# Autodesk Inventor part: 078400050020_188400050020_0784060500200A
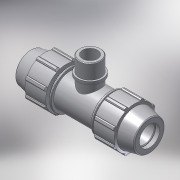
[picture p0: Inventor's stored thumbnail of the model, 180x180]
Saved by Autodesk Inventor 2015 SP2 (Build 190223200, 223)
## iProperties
Created: 2017-02
Part Number: 078400050020_188400050020_0784060500200A
Material: PVC-Piping
Description: PLASSON TEE WITH THREADED MALE OFFTAKE 50-2"
Document SubType Name: Modeling
Designer: KIM
Mass: 92.6774 g
Surface Area: 199.44 cm^2
Volume: 66.1981 cm^3
Density: 1.4 g/cm^3
Appearance: Smooth - White
Author: Кирилл
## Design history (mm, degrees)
derived "07840.ipt"
feature "Solid1::07840.ipt"
feature "Solid2::07840.ipt"
tag "TaggingFeature1"
body "Solid1"
body "Solid2"
other parameters: "d4" = 9.58333, "d5" = 27.6, "d7" = 96, "d11" = 3.83333, "d13" = 120 deg, "d14" = 75, "d15" = 12 deg, "d16" = 83.52, "d18" = 2.5, "d19" = 35 deg, "d20" = 17.5 deg, "d21" = 89.28, "d23" = 0, "d25" = 360 deg, "d27" = 1.92, "d33" = 1, "d42" = 41.4, "d43" = 2.88, "d46" = 1.5, "d68" = 3.83333, "d72" = 82, "d73" = 59.614, "d74" = 26, "d75" = 68.5561, "d76" = 41.7298, "d77" = 31.2, "d80" = 1.78842, "d91" = 72, "d93" = 93, "d95" = 45, "d101" = 0, "d103" = 0, "d105" = 0, "E_" = 96, "A_" = 82, "l_" = 93, "l_2" = 26, "R_" = 59.614
